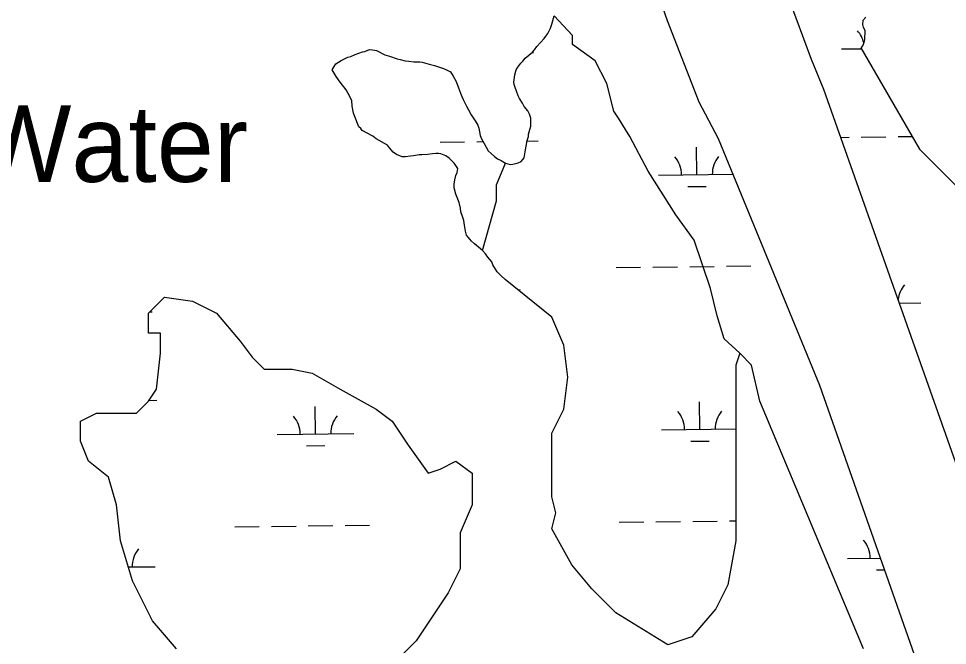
# Model space of a CAD drawing. Extents: x 3694830 to 3732949, y 415201 to 440970.
# Drawn here: x 3699486 to 3700698, y 421291 to 422110 of the extents above; entities that cross this region are included whole.
import ezdxf

# ---------------------------------------------------------------- set-up
doc = ezdxf.new("R2010")
doc.units = 0
for name, color, linetype in [('V-RIVR-IDEN', 7, 'Continuous'), ('V-TOPO-SHOR', 7, 'Continuous'), ('V-WETL-SWMP', 7, 'Continuous')]:
    doc.layers.add(name, color=color, linetype=linetype)

msp = doc.modelspace()

# ---------------------------------------------------------------- linework, layer by layer
at = {"layer": 'V-TOPO-SHOR'}
for p, q in [((3700224.2, 422423.7), (3700332.4, 422107.2)), ((3700521, 422056.4), (3700447.1, 422253.8)), ((3700182, 422102.7), (3700184.9, 422113.5)), ((3700180, 422097.2), (3700182, 422102.7)), ((3700332.4, 422107.2), (3700373.9, 422001.2)), ((3700587.7, 422107.5), (3700587.3, 422102.1)), ((3700587.3, 422102.1), (3700588.4, 422098.5)), ((3700591.7, 422111.7), (3700587.7, 422107.5)), ((3700174, 422086.8), (3700176.4, 422090.3)), ((3700176.4, 422090.3), (3700180, 422097.2)), ((3700588.4, 422098.5), (3700590.3, 422094.6)), ((3700590.3, 422094.6), (3700590, 422082.1)), ((3700162.4, 422073.4), (3700171.6, 422083.7)), ((3700171.6, 422083.7), (3700174, 422086.8)), ((3700589.2, 422078.6), (3700588, 422074.8)), ((3700590, 422082.1), (3700589.2, 422078.6)), ((3699925.2, 422062.9), (3699934.6, 422066.3)), ((3699934.6, 422066.3), (3699937.7, 422067)), ((3699937.7, 422067), (3699943.6, 422069.3)), ((3699943.6, 422069.3), (3699947.5, 422069.2)), ((3699947.5, 422069.2), (3699952.9, 422068.3)), ((3699952.9, 422068.3), (3699963.8, 422062.3)), ((3700147, 422058), (3700156.5, 422066.1)), ((3700156.5, 422066.1), (3700159.2, 422069.1)), ((3700159.2, 422069.1), (3700162.4, 422073.4)), ((3700588, 422074.8), (3700585.2, 422071.7)), ((3700585.2, 422071.7), (3700661.8, 421939.1)), ((3699899.6, 422050.5), (3699906.7, 422055.1)), ((3699906.7, 422055.1), (3699915.4, 422059.2)), ((3699915.4, 422059.2), (3699919.3, 422060.3)), ((3699919.3, 422060.3), (3699925.2, 422062.9)), ((3699963.8, 422062.3), (3699970, 422060.6)), ((3699970, 422060.6), (3699980.1, 422057.3)), ((3699980.1, 422057.3), (3699983.9, 422056.5)), ((3699983.9, 422056.5), (3699990.5, 422054.8)), ((3699990.5, 422054.8), (3699995.2, 422054.3)), ((3699995.2, 422054.3), (3700001.8, 422053.5)), ((3700001.8, 422053.5), (3700009.6, 422053.3)), ((3700009.6, 422053.3), (3700012.7, 422052.9)), ((3700012.7, 422052.9), (3700021.7, 422050.4)), ((3700141.4, 422051.5), (3700143.8, 422054.2)), ((3700143.8, 422054.2), (3700147, 422058)), ((3700537.1, 422017.2), (3700521, 422056.4)), ((3699895.2, 422042.8), (3699897.6, 422047.4)), ((3699900.1, 422034.1), (3699895.2, 422042.8)), ((3699897.6, 422047.4), (3699899.6, 422050.5)), ((3700021.7, 422050.4), (3700028.7, 422048.7)), ((3700028.7, 422048.7), (3700040.3, 422044.6)), ((3700040.3, 422044.6), (3700044.5, 422043)), ((3700044.5, 422043), (3700049.6, 422040.2)), ((3700133.3, 422036.4), (3700135.4, 422043)), ((3700135.4, 422043), (3700137.4, 422046.5)), ((3700137.4, 422046.5), (3700141.4, 422051.5)), ((3699905.5, 422026.6), (3699900.1, 422034.1)), ((3700049.6, 422040.2), (3700053, 422034.7)), ((3700053, 422034.7), (3700056.8, 422027.6)), ((3700132, 422026.7), (3700133.3, 422036.4)), ((3699913.1, 422016.7), (3699905.5, 422026.6)), ((3699916.1, 422012), (3699913.1, 422016.7)), ((3700056.8, 422027.6), (3700060.1, 422019.3)), ((3700060.1, 422019.3), (3700062.4, 422012.3)), ((3700132.7, 422023.6), (3700132, 422026.7)), ((3700133.8, 422020), (3700132.7, 422023.6)), ((3700135.7, 422014.9), (3700133.8, 422020)), ((3700714, 421516.3), (3700537.1, 422017.2)), ((3699920.7, 422003), (3699916.1, 422012)), ((3700062.4, 422012.3), (3700064.2, 422008)), ((3700064.2, 422008), (3700066.1, 422004)), ((3700137.9, 422009), (3700135.7, 422014.9)), ((3700139.8, 422005.5), (3700137.9, 422009)), ((3700143.6, 421999.2), (3700139.8, 422005.5)), ((3699921.3, 421995.5), (3699920.7, 422003)), ((3699922.7, 421986.2), (3699921.3, 421995.5)), ((3700066.1, 422004), (3700070.6, 421995.4)), ((3700070.6, 421995.4), (3700072.9, 421990.6)), ((3700145.9, 421994.9), (3700143.6, 421999.2)), ((3700150.5, 421989.3), (3700145.9, 421994.9)), ((3700373.9, 422001.2), (3700398.8, 421953.2)), ((3699928.3, 421972.8), (3699922.7, 421986.2)), ((3700072.9, 421990.6), (3700076.7, 421984)), ((3700076.7, 421984), (3700082.4, 421974.9)), ((3700152.7, 421985), (3700150.5, 421989.3)), ((3700154.6, 421979.9), (3700152.7, 421985)), ((3700154.4, 421969.4), (3700154.6, 421979.9)), ((3699929.8, 421968.5), (3699928.3, 421972.8)), ((3699932.5, 421966.1), (3699929.8, 421968.5)), ((3700082.4, 421974.9), (3700085.4, 421970.5)), ((3700085.4, 421970.5), (3700086.5, 421966.6)), ((3700151.5, 421958.9), (3700154.4, 421969.4)), ((3699934.4, 421963.7), (3699932.5, 421966.1)), ((3699948.3, 421956.1), (3699934.4, 421963.7)), ((3699952.6, 421952.9), (3699948.3, 421956.1)), ((3700086.5, 421966.6), (3700088.3, 421957.2)), ((3700088.3, 421957.2), (3700090.2, 421952.9)), ((3700149.8, 421950.7), (3700151.5, 421955.8)), ((3700151.5, 421955.8), (3700151.5, 421958.9)), ((3699967.2, 421944.5), (3699952.6, 421952.9)), ((3699969.9, 421940.9), (3699967.2, 421944.5)), ((3700090.2, 421952.9), (3700093.6, 421946.6)), ((3700093.6, 421946.6), (3700095.9, 421941.9)), ((3700147.2, 421935.6), (3700149.8, 421950.7)), ((3700398.8, 421953.2), (3700531.4, 421631.1)), ((3699974.5, 421935.4), (3699969.9, 421940.9)), ((3699979.1, 421932.2), (3699974.5, 421935.4)), ((3699986.5, 421929.3), (3699979.1, 421932.2)), ((3700008.4, 421931.7), (3700001.3, 421930.6)), ((3700011.9, 421932), (3700008.4, 421931.7)), ((3700019.7, 421932.3), (3700011.9, 421932)), ((3700025.9, 421933.3), (3700019.7, 421932.3)), ((3700030.2, 421933.7), (3700025.9, 421933.3)), ((3700033.7, 421933.6), (3700030.2, 421933.7)), ((3700036.8, 421933.2), (3700033.7, 421933.6)), ((3700043.4, 421930.7), (3700036.8, 421933.2)), ((3700095.9, 421941.9), (3700098.9, 421937.2)), ((3700098.9, 421937.2), (3700102.4, 421933.6)), ((3700102.4, 421933.6), (3700107, 421929.6)), ((3700145.5, 421927.8), (3700147.2, 421935.6)), ((3700661.8, 421939.1), (3700719.2, 421881.7)), ((3699990.8, 421929.3), (3699986.5, 421929.3)), ((3699997.4, 421929.9), (3699990.8, 421929.3)), ((3700001.3, 421930.6), (3699997.4, 421929.9)), ((3700047.7, 421927.5), (3700043.4, 421930.7)), ((3700054.2, 421920.8), (3700047.7, 421927.5)), ((3700056.5, 421918), (3700054.2, 421920.8)), ((3700107, 421929.6), (3700110.8, 421926.8)), ((3700110.8, 421926.8), (3700115.5, 421924.4)), ((3700115.5, 421924.4), (3700121.2, 421920.8)), ((3700121.2, 421920.8), (3700127.5, 421919.1)), ((3700127.5, 421919.1), (3700131, 421919.5)), ((3700131, 421919.5), (3700138, 421921.3)), ((3700138, 421921.3), (3700141.6, 421923.2)), ((3700141.6, 421923.2), (3700145.5, 421927.8)), ((3700059.1, 421914.1), (3700056.5, 421918)), ((3700056.6, 421904.7), (3700058.3, 421908.6)), ((3700058.3, 421908.6), (3700059.1, 421914.1)), ((3700054.5, 421893.5), (3700055, 421899.3)), ((3700055, 421899.3), (3700056.6, 421904.7)), ((3700054.4, 421888.8), (3700054.5, 421893.5)), ((3700056.6, 421880.6), (3700054.4, 421888.8)), ((3700060.7, 421869.6), (3700056.6, 421880.6)), ((3700062.5, 421862.1), (3700060.7, 421869.6)), ((3700063.2, 421857.5), (3700062.5, 421862.1)), ((3700065.5, 421850), (3700063.2, 421857.5)), ((3700067, 421846.1), (3700065.5, 421850)), ((3700067.6, 421839.8), (3700067, 421846.1)), ((3700069.1, 421832), (3700067.6, 421839.8)), ((3700070.5, 421826.9), (3700069.1, 421832)), ((3700077, 421819), (3700070.5, 421826.9)), ((3700080.9, 421815.8), (3700077, 421819)), ((3700091.2, 421806.7), (3700080.9, 421815.8)), ((3700095.1, 421802.7), (3700091.2, 421806.7)), ((3700098.1, 421798.4), (3700095.1, 421802.7)), ((3700103.5, 421792), (3700098.1, 421798.4)), ((3700104.6, 421788.1), (3700103.5, 421792)), ((3700108.4, 421782.6), (3700104.6, 421788.1)), ((3700110.3, 421779.1), (3700108.4, 421782.6)), ((3700115.6, 421773.9), (3700110.3, 421779.1)), ((3700121, 421769.1), (3700115.6, 421773.9)), ((3700181.9, 421719.9), (3700121, 421769.1)), ((3699655.1, 421725.1), (3699676, 421746)), ((3699676, 421746), (3699712.5, 421740.7)), ((3699712.5, 421740.7), (3699743.8, 421725.1)), ((3699655.1, 421699), (3699655.1, 421725.1)), ((3699743.8, 421725.1), (3699775.1, 421688.6)), ((3700197.6, 421683.3), (3700181.9, 421719.9)), ((3699670.8, 421699), (3699655.1, 421699)), ((3699670.8, 421672.9), (3699670.8, 421699)), ((3699775.1, 421688.6), (3699790.7, 421667.7)), ((3700202.8, 421641.6), (3700197.6, 421683.3)), ((3699665.6, 421625.9), (3699670.8, 421672.9)), ((3699790.7, 421667.7), (3699806.4, 421652)), ((3700427.1, 421672.9), (3700421.9, 421657.2)), ((3700442.7, 421657.2), (3700427.1, 421672.9)), ((3700421.9, 421657.2), (3700421.9, 421427.6)), ((3700453.2, 421610.3), (3700442.7, 421657.2)), ((3699806.4, 421652), (3699842.9, 421652)), ((3699842.9, 421652), (3699869, 421646.8)), ((3699869, 421646.8), (3699905.5, 421625.9)), ((3700197.6, 421599.8), (3700202.8, 421641.6)), ((3700531.4, 421631.1), (3700698.3, 421156.2)), ((3699655.1, 421610.3), (3699665.6, 421625.9)), ((3699905.5, 421625.9), (3699952.4, 421599.8)), ((3699639.5, 421594.6), (3699655.1, 421610.3)), ((3700588.8, 421286.7), (3700453.2, 421610.3)), ((3699566.5, 421584.2), (3699587.3, 421594.6)), ((3699587.3, 421594.6), (3699639.5, 421594.6)), ((3699952.4, 421599.8), (3699973.3, 421584.2)), ((3700181.9, 421568.5), (3700197.6, 421599.8)), ((3699566.5, 421558.1), (3699566.5, 421584.2)), ((3699973.3, 421584.2), (3699994.2, 421552.9)), ((3700181.9, 421485), (3700181.9, 421568.5)), ((3699576.9, 421532), (3699566.5, 421558.1)), ((3699994.2, 421552.9), (3700020.2, 421516.3)), ((3699603, 421511.1), (3699576.9, 421532)), ((3700035.9, 421521.5), (3700056.7, 421532)), ((3700056.7, 421532), (3700077.6, 421516.3)), ((3700020.2, 421516.3), (3700035.9, 421521.5)), ((3699613.4, 421474.6), (3699603, 421511.1)), ((3700077.6, 421516.3), (3700077.6, 421474.6)), ((3700187.1, 421464.1), (3700181.9, 421485)), ((3699618.6, 421427.6), (3699613.4, 421474.6)), ((3700077.6, 421474.6), (3700062, 421438)), ((3700181.9, 421443.3), (3700187.1, 421464.1)), ((3700062, 421438), (3700062, 421391.1)), ((3700208, 421396.3), (3700181.9, 421443.3)), ((3699634.3, 421375.4), (3699618.6, 421427.6)), ((3700421.9, 421427.6), (3700411.4, 421370.2)), ((3700062, 421391.1), (3700046.3, 421359.8)), ((3700234.1, 421365), (3700208, 421396.3)), ((3699660.3, 421323.2), (3699634.3, 421375.4)), ((3700265.4, 421333.7), (3700234.1, 421365)), ((3700411.4, 421370.2), (3700395.8, 421338.9)), ((3700046.3, 421359.8), (3700004.6, 421297.1)), ((3700395.8, 421338.9), (3700364.5, 421302.3)), ((3700333.2, 421291.9), (3700265.4, 421333.7)), ((3699691.6, 421286.7), (3699660.3, 421323.2)), ((3700364.5, 421302.3), (3700333.2, 421291.9)), ((3700004.6, 421297.1), (3699957.6, 421250.2))]:
    msp.add_line(p, q, dxfattribs=at)
for points in [[(3700427.1, 421672.9), (3700406.8, 421691.4), (3700397.8, 421721.5), (3700388.8, 421757.5), (3700367.8, 421820.6), (3700343.7, 421853.6), (3700307.7, 421910.7), (3700283.7, 421955.7), (3700268.7, 421979.7), (3700262.7, 421988.7), (3700253.7, 422024.8), (3700238.6, 422054.8), (3700208.6, 422075.8), (3700208.6, 422087.9), (3700184.9, 422113.5)], [(3700091.2, 421806.7), (3700109.5, 421871.6), (3700109.5, 421892.6), (3700121.2, 421920.8)]]:
    msp.add_lwpolyline(points, dxfattribs=at)
at = {"layer": 'V-WETL-SWMP'}
for p, q in [((3700224.2, 422423.7), (3700332.4, 422107.2)), ((3700521, 422056.4), (3700447.1, 422253.8)), ((3700182, 422102.7), (3700184.9, 422113.5)), ((3700180, 422097.2), (3700182, 422102.7)), ((3700332.4, 422107.2), (3700373.9, 422001.2)), ((3700587.7, 422107.5), (3700587.3, 422102.1)), ((3700587.3, 422102.1), (3700588.4, 422098.5)), ((3700591.7, 422111.7), (3700587.7, 422107.5)), ((3700174, 422086.8), (3700176.4, 422090.3)), ((3700176.4, 422090.3), (3700180, 422097.2)), ((3700588.4, 422098.5), (3700590.3, 422094.6)), ((3700590.3, 422094.6), (3700590, 422082.1)), ((3700162.4, 422073.4), (3700171.6, 422083.7)), ((3700171.6, 422083.7), (3700174, 422086.8)), ((3700589.2, 422078.6), (3700588, 422074.8)), ((3700590, 422082.1), (3700589.2, 422078.6)), ((3699925.2, 422062.9), (3699934.6, 422066.3)), ((3699934.6, 422066.3), (3699937.7, 422067)), ((3699937.7, 422067), (3699943.6, 422069.3)), ((3699943.6, 422069.3), (3699947.5, 422069.2)), ((3699947.5, 422069.2), (3699952.9, 422068.3)), ((3699952.9, 422068.3), (3699963.8, 422062.3)), ((3700147, 422058), (3700156.5, 422066.1)), ((3700155.6, 422065.3), (3700157.9, 422065.3)), ((3700156.5, 422066.1), (3700159.2, 422069.1)), ((3700159.2, 422069.1), (3700162.4, 422073.4)), ((3700559.8, 422070.1), (3700585.9, 422070.4)), ((3700588, 422074.8), (3700585.2, 422071.7)), ((3700585.2, 422071.7), (3700661.8, 421939.1)), ((3699899.6, 422050.5), (3699906.7, 422055.1)), ((3699906.7, 422055.1), (3699915.4, 422059.2)), ((3699915.4, 422059.2), (3699919.3, 422060.3)), ((3699919.3, 422060.3), (3699925.2, 422062.9)), ((3699963.8, 422062.3), (3699970, 422060.6)), ((3699970, 422060.6), (3699980.1, 422057.3)), ((3699980.1, 422057.3), (3699983.9, 422056.5)), ((3699983.9, 422056.5), (3699990.5, 422054.8)), ((3699990.5, 422054.8), (3699995.2, 422054.3)), ((3699995.2, 422054.3), (3700001.8, 422053.5)), ((3700001.8, 422053.5), (3700009.6, 422053.3)), ((3700009.6, 422053.3), (3700012.7, 422052.9)), ((3700012.7, 422052.9), (3700021.7, 422050.4)), ((3700141.4, 422051.5), (3700143.8, 422054.2)), ((3700143.8, 422054.2), (3700147, 422058)), ((3700537.1, 422017.2), (3700521, 422056.4)), ((3699895.2, 422042.8), (3699897.6, 422047.4)), ((3699900.1, 422034.1), (3699895.2, 422042.8)), ((3699897.6, 422047.4), (3699899.6, 422050.5)), ((3700021.7, 422050.4), (3700028.7, 422048.7)), ((3700028.7, 422048.7), (3700040.3, 422044.6)), ((3700040.3, 422044.6), (3700044.5, 422043)), ((3700044.5, 422043), (3700049.6, 422040.2)), ((3700133.3, 422036.4), (3700135.4, 422043)), ((3700135.4, 422043), (3700137.4, 422046.5)), ((3700137.4, 422046.5), (3700141.4, 422051.5)), ((3699905.5, 422026.6), (3699900.1, 422034.1)), ((3700049.6, 422040.2), (3700053, 422034.7)), ((3700053, 422034.7), (3700056.8, 422027.6)), ((3700132, 422026.7), (3700133.3, 422036.4)), ((3699913.1, 422016.7), (3699905.5, 422026.6)), ((3699916.1, 422012), (3699913.1, 422016.7)), ((3700056.8, 422027.6), (3700060.1, 422019.3)), ((3700060.1, 422019.3), (3700062.4, 422012.3)), ((3700132.7, 422023.6), (3700132, 422026.7)), ((3700133.8, 422020), (3700132.7, 422023.6)), ((3700135.7, 422014.9), (3700133.8, 422020)), ((3700714, 421516.3), (3700537.1, 422017.2)), ((3699920.7, 422003), (3699916.1, 422012)), ((3700062.4, 422012.3), (3700064.2, 422008)), ((3700064.2, 422008), (3700066.1, 422004)), ((3700137.9, 422009), (3700135.7, 422014.9)), ((3700139.8, 422005.5), (3700137.9, 422009)), ((3700143.6, 421999.2), (3700139.8, 422005.5)), ((3699921.3, 421995.5), (3699920.7, 422003)), ((3699922.7, 421986.2), (3699921.3, 421995.5)), ((3700066.1, 422004), (3700070.6, 421995.4)), ((3700070.6, 421995.4), (3700072.9, 421990.6)), ((3700145.9, 421994.9), (3700143.6, 421999.2)), ((3700150.5, 421989.3), (3700145.9, 421994.9)), ((3700373.9, 422001.2), (3700398.8, 421953.2)), ((3699928.3, 421972.8), (3699922.7, 421986.2)), ((3700072.9, 421990.6), (3700076.7, 421984)), ((3700076.7, 421984), (3700082.4, 421974.9)), ((3700152.7, 421985), (3700150.5, 421989.3)), ((3700154.6, 421979.9), (3700152.7, 421985)), ((3700154.4, 421969.4), (3700154.6, 421979.9)), ((3699929.8, 421968.5), (3699928.3, 421972.8)), ((3699932.5, 421966.1), (3699929.8, 421968.5)), ((3700082.4, 421974.9), (3700085.4, 421970.5)), ((3700085.4, 421970.5), (3700086.5, 421966.6)), ((3700151.5, 421958.9), (3700154.4, 421969.4)), ((3699934.4, 421963.7), (3699932.5, 421966.1)), ((3699948.3, 421956.1), (3699934.4, 421963.7)), ((3699952.6, 421952.9), (3699948.3, 421956.1)), ((3700086.5, 421966.6), (3700088.3, 421957.2)), ((3700088.3, 421957.2), (3700090.2, 421952.9)), ((3700149.8, 421950.7), (3700151.5, 421955.8)), ((3700151.5, 421955.8), (3700151.5, 421958.9)), ((3700633.8, 421955.6), (3700652.1, 421955.8)), ((3699967.2, 421944.5), (3699952.6, 421952.9)), ((3699969.9, 421940.9), (3699967.2, 421944.5)), ((3700035.9, 421948.4), (3700067.8, 421948.8)), ((3700083.8, 421949), (3700092.3, 421949.1)), ((3700090.2, 421952.9), (3700093.6, 421946.6)), ((3700093.6, 421946.6), (3700095.9, 421941.9)), ((3700147.2, 421935.6), (3700149.8, 421950.7)), ((3700149.7, 421949.8), (3700163.8, 421950)), ((3700398.8, 421953.2), (3700531.4, 421631.1)), ((3700559.2, 421954.7), (3700569.8, 421954.8)), ((3700585.8, 421955), (3700617.8, 421955.4)), ((3699974.5, 421935.4), (3699969.9, 421940.9)), ((3699979.1, 421932.2), (3699974.5, 421935.4)), ((3699986.5, 421929.3), (3699979.1, 421932.2)), ((3700008.4, 421931.7), (3700001.3, 421930.6)), ((3700011.9, 421932), (3700008.4, 421931.7)), ((3700019.7, 421932.3), (3700011.9, 421932)), ((3700025.9, 421933.3), (3700019.7, 421932.3)), ((3700030.2, 421933.7), (3700025.9, 421933.3)), ((3700033.7, 421933.6), (3700030.2, 421933.7)), ((3700036.8, 421933.2), (3700033.7, 421933.6)), ((3700043.4, 421930.7), (3700036.8, 421933.2)), ((3700095.9, 421941.9), (3700098.9, 421937.2)), ((3700098.9, 421937.2), (3700102.4, 421933.6)), ((3700102.4, 421933.6), (3700107, 421929.6)), ((3700145.5, 421927.8), (3700147.2, 421935.6)), ((3700371.2, 421906), (3700370.8, 421942)), ((3700661.8, 421939.1), (3700719.2, 421881.7)), ((3699990.8, 421929.3), (3699986.5, 421929.3)), ((3699997.4, 421929.9), (3699990.8, 421929.3)), ((3700001.3, 421930.6), (3699997.4, 421929.9)), ((3700047.7, 421927.5), (3700043.4, 421930.7)), ((3700054.2, 421920.8), (3700047.7, 421927.5)), ((3700056.5, 421918), (3700054.2, 421920.8)), ((3700107, 421929.6), (3700110.8, 421926.8)), ((3700110.8, 421926.8), (3700115.5, 421924.4)), ((3700115.5, 421924.4), (3700121.2, 421920.8)), ((3700121.2, 421920.8), (3700127.5, 421919.1)), ((3700127.5, 421919.1), (3700131, 421919.5)), ((3700131, 421919.5), (3700138, 421921.3)), ((3700138, 421921.3), (3700141.6, 421923.2)), ((3700141.6, 421923.2), (3700145.5, 421927.8)), ((3700059.1, 421914.1), (3700056.5, 421918)), ((3700056.6, 421904.7), (3700058.3, 421908.6)), ((3700058.3, 421908.6), (3700059.1, 421914.1)), ((3700054.5, 421893.5), (3700055, 421899.3)), ((3700055, 421899.3), (3700056.6, 421904.7)), ((3700321.2, 421905.4), (3700418, 421906.6)), ((3700054.4, 421888.8), (3700054.5, 421893.5)), ((3700056.6, 421880.6), (3700054.4, 421888.8)), ((3700359.4, 421890.4), (3700383.4, 421890.7)), ((3700060.7, 421869.6), (3700056.6, 421880.6)), ((3700062.5, 421862.1), (3700060.7, 421869.6)), ((3700063.2, 421857.5), (3700062.5, 421862.1)), ((3700065.5, 421850), (3700063.2, 421857.5)), ((3700067, 421846.1), (3700065.5, 421850)), ((3700067.6, 421839.8), (3700067, 421846.1)), ((3700069.1, 421832), (3700067.6, 421839.8)), ((3700070.5, 421826.9), (3700069.1, 421832)), ((3700077, 421819), (3700070.5, 421826.9)), ((3700080.9, 421815.8), (3700077, 421819)), ((3700091.2, 421806.7), (3700080.9, 421815.8)), ((3700095.1, 421802.7), (3700091.2, 421806.7)), ((3700098.1, 421798.4), (3700095.1, 421802.7)), ((3700103.5, 421792), (3700098.1, 421798.4)), ((3700104.6, 421788.1), (3700103.5, 421792)), ((3700108.4, 421782.6), (3700104.6, 421788.1)), ((3700361.8, 421785.8), (3700393.8, 421786.2)), ((3700409.8, 421786.4), (3700441.8, 421786.8)), ((3700110.3, 421779.1), (3700108.4, 421782.6)), ((3700115.6, 421773.9), (3700110.3, 421779.1)), ((3700121, 421769.1), (3700115.6, 421773.9)), ((3700265.8, 421784.7), (3700297.8, 421785.1)), ((3700313.8, 421785.2), (3700345.8, 421785.6)), ((3700181.9, 421719.9), (3700121, 421769.1)), ((3699655.1, 421725.1), (3699676, 421746)), ((3699676, 421746), (3699712.5, 421740.7)), ((3699712.5, 421740.7), (3699743.8, 421725.1)), ((3700635.6, 421738.3), (3700663.8, 421738.7)), ((3699656.7, 421726.7), (3699660, 421726.7)), ((3699655.1, 421699), (3699655.1, 421725.1)), ((3699743.8, 421725.1), (3699775.1, 421688.6)), ((3700197.6, 421683.3), (3700181.9, 421719.9)), ((3699670.8, 421699), (3699655.1, 421699)), ((3699670.8, 421672.9), (3699670.8, 421699)), ((3699775.1, 421688.6), (3699790.7, 421667.7)), ((3700202.8, 421641.6), (3700197.6, 421683.3)), ((3699665.6, 421625.9), (3699670.8, 421672.9)), ((3699790.7, 421667.7), (3699806.4, 421652)), ((3700427.1, 421672.9), (3700421.9, 421657.2)), ((3700442.7, 421657.2), (3700427.1, 421672.9)), ((3700421.9, 421657.2), (3700421.9, 421427.6)), ((3700453.2, 421610.3), (3700442.7, 421657.2)), ((3699806.4, 421652), (3699842.9, 421652)), ((3699842.9, 421652), (3699869, 421646.8)), ((3699869, 421646.8), (3699905.5, 421625.9)), ((3700197.6, 421599.8), (3700202.8, 421641.6)), ((3700531.4, 421631.1), (3700698.3, 421156.2)), ((3699655.1, 421610.3), (3699665.6, 421625.9)), ((3699905.5, 421625.9), (3699952.4, 421599.8)), ((3699639.5, 421594.6), (3699655.1, 421610.3)), ((3699655.7, 421611.2), (3699665.9, 421611.3)), ((3700375.2, 421573.4), (3700374.8, 421609.4)), ((3700588.8, 421286.7), (3700453.2, 421610.3)), ((3699566.5, 421584.2), (3699587.3, 421594.6)), ((3699587.3, 421594.6), (3699639.5, 421594.6)), ((3699873.3, 421567.4), (3699872.9, 421603.4)), ((3699952.4, 421599.8), (3699973.3, 421584.2)), ((3700181.9, 421568.5), (3700197.6, 421599.8)), ((3699566.5, 421558.1), (3699566.5, 421584.2)), ((3699973.3, 421584.2), (3699994.2, 421552.9)), ((3699823.3, 421566.8), (3699923.3, 421568)), ((3700181.9, 421485), (3700181.9, 421568.5)), ((3700325.2, 421572.8), (3700421.9, 421573.9)), ((3699576.9, 421532), (3699566.5, 421558.1)), ((3700363.4, 421557.8), (3700387.4, 421558.1)), ((3699861.5, 421551.8), (3699885.5, 421552.1)), ((3699994.2, 421552.9), (3700020.2, 421516.3)), ((3699603, 421511.1), (3699576.9, 421532)), ((3700035.9, 421521.5), (3700056.7, 421532)), ((3700056.7, 421532), (3700077.6, 421516.3)), ((3700020.2, 421516.3), (3700035.9, 421521.5)), ((3699613.4, 421474.6), (3699603, 421511.1)), ((3700077.6, 421516.3), (3700077.6, 421474.6)), ((3700187.1, 421464.1), (3700181.9, 421485)), ((3699618.6, 421427.6), (3699613.4, 421474.6)), ((3700077.6, 421474.6), (3700062, 421438)), ((3700181.9, 421443.3), (3700187.1, 421464.1)), ((3699767.9, 421446), (3699799.9, 421446.4)), ((3699815.9, 421446.6), (3699847.9, 421447)), ((3699863.9, 421447.2), (3699895.9, 421447.6)), ((3699911.9, 421447.7), (3699943.9, 421448.1)), ((3700269.8, 421452), (3700301.8, 421452.4)), ((3700317.8, 421452.6), (3700349.8, 421453)), ((3700365.8, 421453.2), (3700397.8, 421453.5)), ((3700413.8, 421453.7), (3700421.9, 421453.8)), ((3700062, 421438), (3700062, 421391.1)), ((3700208, 421396.3), (3700181.9, 421443.3)), ((3699634.3, 421375.4), (3699618.6, 421427.6)), ((3700421.9, 421427.6), (3700411.4, 421370.2)), ((3700567.7, 421404.8), (3700610.7, 421405.3)), ((3699628.8, 421393.6), (3699663.9, 421394)), ((3700062, 421391.1), (3700046.3, 421359.8)), ((3700234.1, 421365), (3700208, 421396.3)), ((3700605.9, 421389.9), (3700616.1, 421390)), ((3699660.3, 421323.2), (3699634.3, 421375.4)), ((3700265.4, 421333.7), (3700234.1, 421365)), ((3700411.4, 421370.2), (3700395.8, 421338.9)), ((3700046.3, 421359.8), (3700004.6, 421297.1)), ((3700395.8, 421338.9), (3700364.5, 421302.3)), ((3700333.2, 421291.9), (3700265.4, 421333.7)), ((3699691.6, 421286.7), (3699660.3, 421323.2)), ((3700364.5, 421302.3), (3700333.2, 421291.9)), ((3700004.6, 421297.1), (3699957.6, 421250.2))]:
    msp.add_line(p, q, dxfattribs=at)
for centre, start, end in [((3700554.6, 422070.5), 12.226, 41.4552), ((3700316, 421905.8), 359.9115, 41.4552), ((3700426.5, 421907.1), 139.9115, 181.4552), ((3700669, 421739.2), 139.9115, 173.9501), ((3700167.1, 421733.2), 139.9115, 142.7242), ((3700319.9, 421573.2), 359.9115, 41.4552), ((3700430.4, 421574.5), 139.9115, 181.4552), ((3699818.1, 421567.2), 359.9115, 41.4552), ((3699928.5, 421568.5), 139.9115, 181.4552), ((3700562.4, 421405.2), 359.9115, 41.4552), ((3699669.2, 421394.6), 139.9115, 181.4552)]:
    msp.add_arc(centre, 35.2, start, end, dxfattribs=at)

# ---------------------------------------------------------------- texts
at = {"layer": 'V-RIVR-IDEN'}
msp.add_text('Water', height=100, dxfattribs=at).set_placement((3699428.4, 421896.5))

doc.saveas('drawing.dxf')
